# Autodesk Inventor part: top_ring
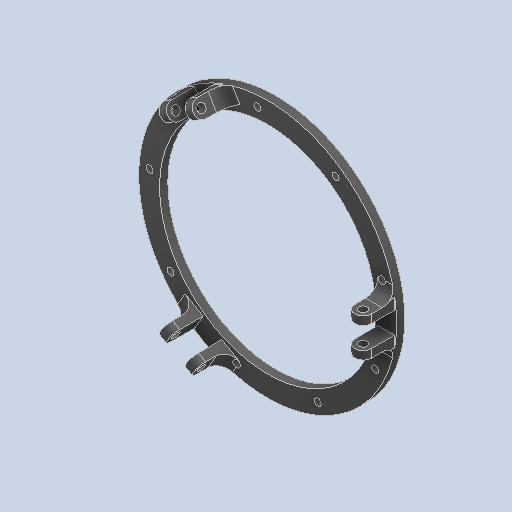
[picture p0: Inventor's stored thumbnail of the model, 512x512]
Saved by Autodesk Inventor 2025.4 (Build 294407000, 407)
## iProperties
Created: 2026-09
Part Number: top_ring
Material: Generic
Document SubType Name: Modeling
Designer: AdminForWorker
Density: 1 g/cm^3
Appearance: Default
Title: top_ring v2 v1
Author: AdminForWorker
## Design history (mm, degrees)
feature "Body1"
body "Solid1"
